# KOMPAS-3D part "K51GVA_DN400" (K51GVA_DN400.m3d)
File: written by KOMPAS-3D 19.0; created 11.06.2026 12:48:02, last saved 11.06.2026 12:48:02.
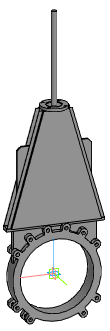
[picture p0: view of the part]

Document properties: Автор: Энергия; Полное имя файла: Z:\3.Личные\kachalov\001_3d для проектировщиков\2.6 Тип_K51GVA. Задвижка\_stp\_stp_K51GVA_DN50-DN1000_с фланцем\K51GVA_DN400.m3d

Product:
- Part/product: K51GVA_DN400

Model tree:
1. Операция без истории:1  (labels: K51GVA_DN400)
